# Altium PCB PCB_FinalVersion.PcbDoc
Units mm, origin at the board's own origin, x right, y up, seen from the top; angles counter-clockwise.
Board outline 269.9 x 119.9 mm, 2 copper layers (Top Layer, Bottom Layer); 58 components, 78 nets, 213 pads, 10 vias.
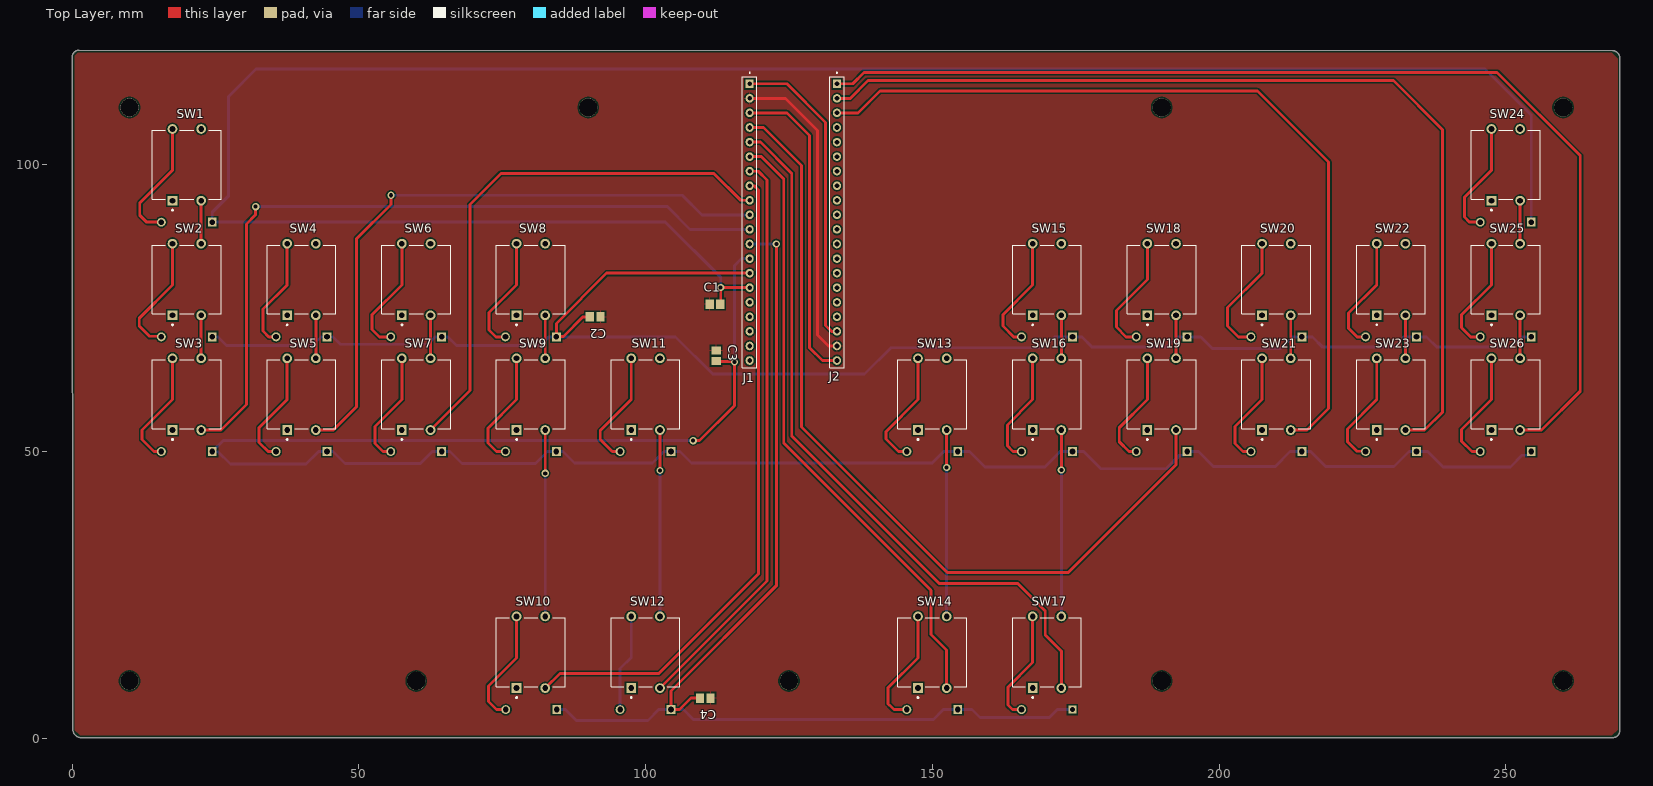
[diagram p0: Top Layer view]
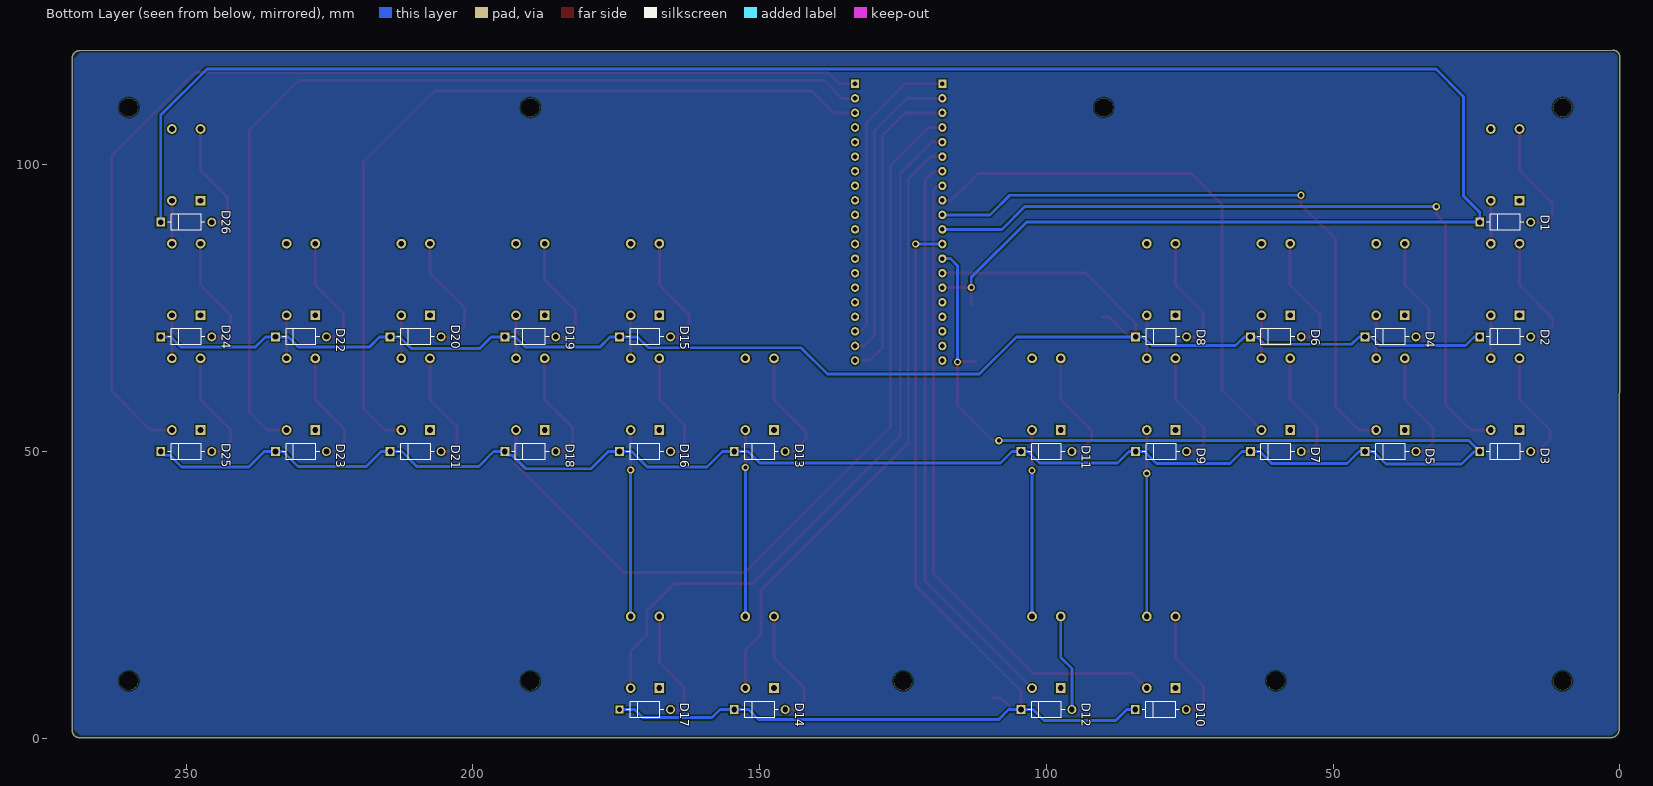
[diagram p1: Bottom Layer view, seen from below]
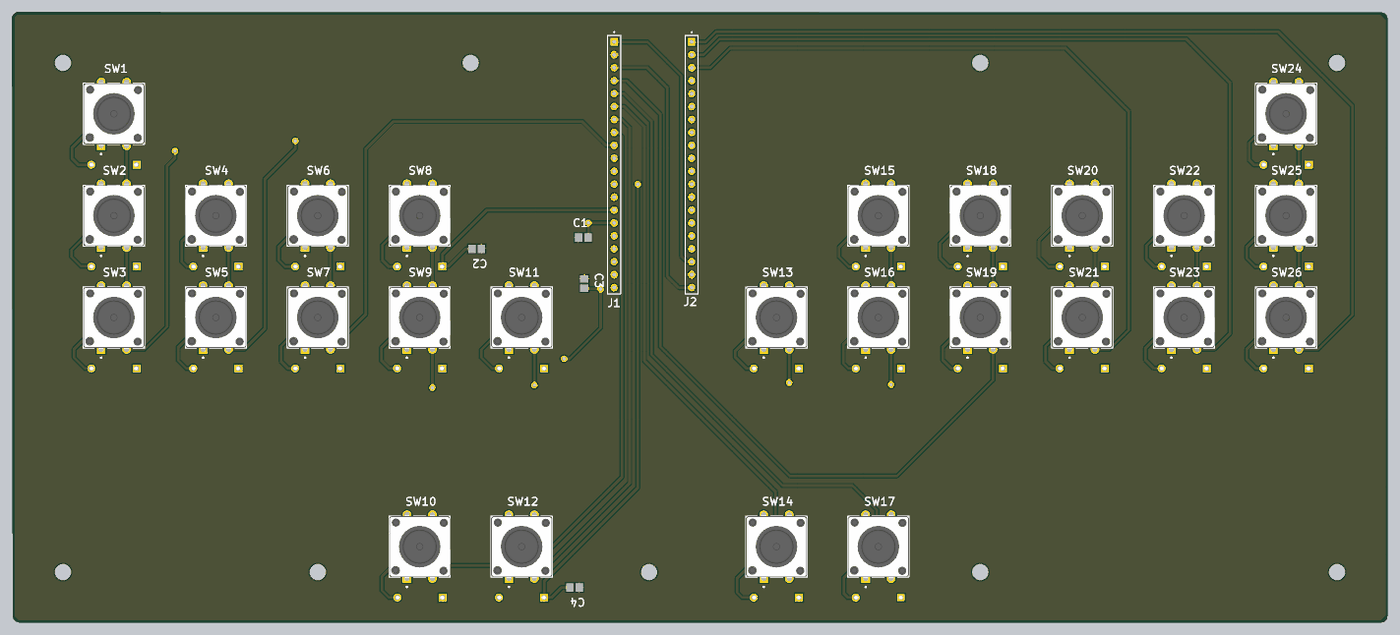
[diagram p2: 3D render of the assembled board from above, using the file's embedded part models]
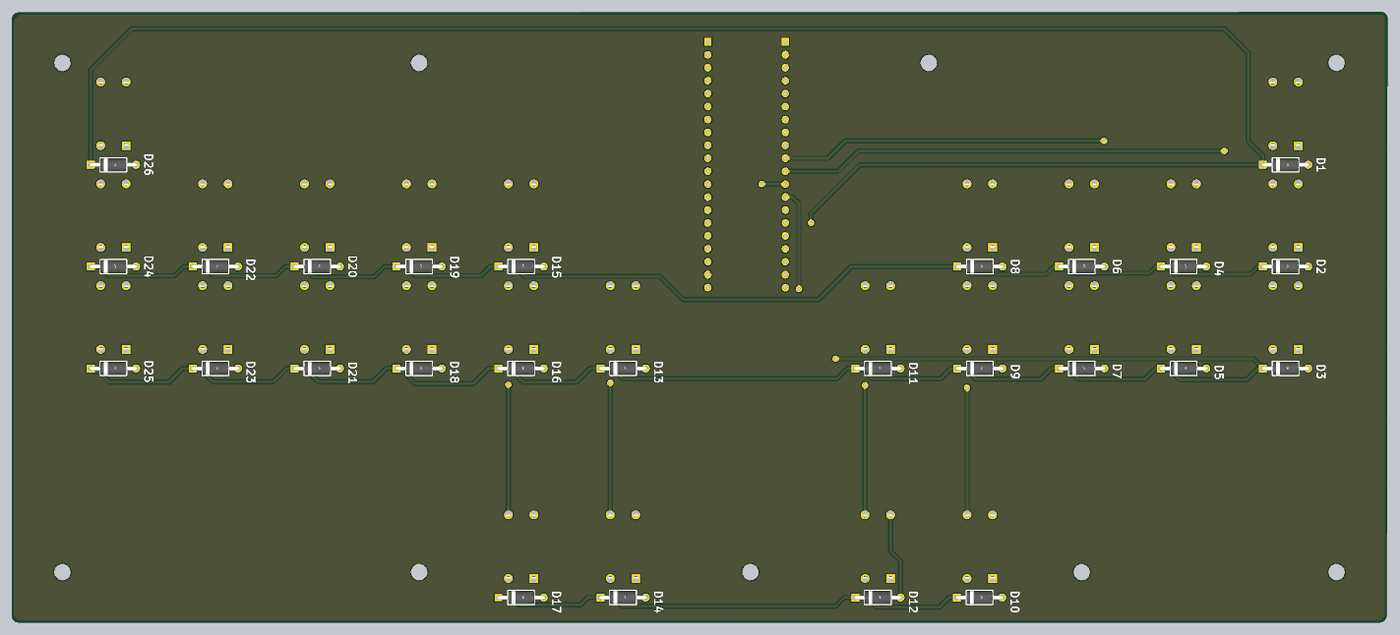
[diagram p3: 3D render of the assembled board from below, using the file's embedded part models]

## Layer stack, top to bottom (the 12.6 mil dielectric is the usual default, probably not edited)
Top Solder: solder mask 0.0102, Solder Resist, Dk 3.5
Top Layer: signal copper 0.0356
Dielectric 1: dielectric 0.32, FR-4, Dk 4.8
Bottom Layer: signal copper 0.0356
Bottom Solder: solder mask 0.0102, Solder Resist, Dk 3.5

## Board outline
0.129,1.541 ccw(c1.57,1.541) 1.57,0.1 5,0.1 268.63,0.1 ccw(c268.63,1.37) 269.9,1.37 269.9,118.63 ccw(c268.63,118.63) 268.63,119.9 1.217,120 ccw(c1.217,118.783) 0,118.783

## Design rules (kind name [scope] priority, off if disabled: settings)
Clearance [All] p1: gap=0.254 ignorepadtopadclearanceinfootprint=FALSE except(0: Arc-Hole Track-Hole SMDPad-Hole THPad-Hole Via-Hole Fill-Hole Poly-Hole Region-Hole Text-Hole)
PolygonConnect [All] p1: connectstyle=Relief reliefconductorwidth=0.254 reliefentries=4 polygonreliefangle="90 Angle" airgapwidth=0.254
RoutingVias [All] p1: holewidth=0.711 width=1.27 viastyle="Through Hole" minholewidth=0.711 minwidth=1.27 maxholewidth=0.711 maxwidth=1.27
SolderMaskExpansion [All] p1: expansion=0.102 istentingtop=FALSE
Width [All] p1: maxlimit=0.5 minlimit=0.254 preferedwidth=0.3
30 further rules are at their usual default settings.

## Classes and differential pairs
component class Sheet1: * A B C1 C2 C3 C4 D D1 D2 D3 D4 D5 D6 D7 D8 D9 D10 D11 D12 D13 D14 D15 D16 D17 D18 D19 D20 D21 D22 D23 D24 D25 D26 E F G H J1 J2 K L O P R S "Special 1" "Special 2" T U W Z

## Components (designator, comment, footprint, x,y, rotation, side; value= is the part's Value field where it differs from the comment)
C1 "TACR107M003XTA" CAPC2014X150X70ML20 112.1,75.7 r0 top
C2 "TACR107M003XTA" CAPC2014X150X70ML20 91.2,73.5 r180 top
C3 "TACR107M003XTA" CAPC2014X150X70ML20 112.3,66.7 r270 top
C4 "TACR107M003XTA" CAPC2014X150X70ML20 110.4,7 r180 top
D1 "1N4007" FP-1N4007-MFG#1 20,90 r180 bottom value=15pF
D2 "1N4007" FP-1N4007-MFG#1 20,70 r180 bottom value=15pF
D3 "1N4007" FP-1N4007-MFG#1 20,50 r180 bottom value=15pF
D4 "1N4007" FP-1N4007-MFG#1 40,70 r180 bottom value=15pF
D5 "1N4007" FP-1N4007-MFG#1 40,50 r180 bottom value=15pF
D6 "1N4007" FP-1N4007-MFG#1 60,70 r180 bottom value=15pF
D7 "1N4007" FP-1N4007-MFG#1 60,50 r180 bottom value=15pF
D8 "1N4007" FP-1N4007-MFG#1 80,70 r180 bottom value=15pF
D9 "1N4007" FP-1N4007-MFG#1 80,50 r180 bottom value=15pF
D10 "1N4007" FP-1N4007-MFG#1 80.061,5 r180 bottom value=15pF
D11 "1N4007" FP-1N4007-MFG#1 100,50 r180 bottom value=15pF
D12 "1N4007" FP-1N4007-MFG#1 100,5 r180 bottom value=15pF
D13 "1N4007" FP-1N4007-MFG#1 150,50 r180 bottom value=15pF
D14 "1N4007" FP-1N4007-MFG#1 150,5 r180 bottom value=15pF
D15 "1N4007" FP-1N4007-MFG#1 170,70 r180 bottom value=15pF
D16 "1N4007" FP-1N4007-MFG#1 170,50 r180 bottom value=15pF
D17 "1N4007" FP-1N4007-MFG#2 170,5 r180 bottom value=15pF
D18 "1N4007" FP-1N4007-MFG#1 190,50 r180 bottom value=15pF
D19 "1N4007" FP-1N4007-MFG#1 190,70 r180 bottom value=15pF
D20 "1N4007" FP-1N4007-MFG#1 210,70 r180 bottom value=15pF
D21 "1N4007" FP-1N4007-MFG#1 210,50 r180 bottom value=15pF
D22 "1N4007" FP-1N4007-MFG#1 230,70 r180 bottom value=15pF
D23 "1N4007" FP-1N4007-MFG#1 230,50 r180 bottom value=15pF
D24 "1N4007" FP-1N4007-MFG#1 250,70 r180 bottom value=15pF
D25 "1N4007" FP-1N4007-MFG#1 250,50 r180 bottom value=15pF
D26 "1N4007" FP-1N4007-MFG#1 250,90 r180 bottom value=15pF
J1 "TS-120-T-AA" SAMTEC_TS-120-T-AA 118.156,90 r270 top
J2 "TS-120-T-AA" SAMTEC_TS-120-T-AA 133.376,90 r270 top
SW1 "MJTP1212A" FP-MJTP1212A-MFG 20,100 r90 top
SW2 "MJTP1212A" FP-MJTP1212A-MFG 20,80 r90 top
SW3 "MJTP1212A" FP-MJTP1212A-MFG 20,60 r90 top
SW4 "MJTP1212A" FP-MJTP1212A-MFG 40,80 r90 top
SW5 "MJTP1212A" FP-MJTP1212A-MFG 40,60 r90 top
SW6 "MJTP1212A" FP-MJTP1212A-MFG 60,80 r90 top
SW7 "MJTP1212A" FP-MJTP1212A-MFG 60,60 r90 top
SW8 "MJTP1212A" FP-MJTP1212A-MFG 80,80 r90 top
SW9 "MJTP1212A" FP-MJTP1212A-MFG 80,60 r90 top
SW10 "MJTP1212A" FP-MJTP1212A-MFG 80,15 r90 top
SW11 "MJTP1212A" FP-MJTP1212A-MFG 100,60 r90 top
SW12 "MJTP1212A" FP-MJTP1212A-MFG 100,15 r90 top
SW13 "MJTP1212A" FP-MJTP1212A-MFG 150,60 r90 top
SW14 "MJTP1212A" FP-MJTP1212A-MFG 150,15 r90 top
SW15 "MJTP1212A" FP-MJTP1212A-MFG 170,80 r90 top
SW16 "MJTP1212A" FP-MJTP1212A-MFG 170,60 r90 top
SW17 "MJTP1212A" FP-MJTP1212A-MFG 170,15 r90 top
SW18 "MJTP1212A" FP-MJTP1212A-MFG 190,80 r90 top
SW19 "MJTP1212A" FP-MJTP1212A-MFG 190,60 r90 top
SW20 "MJTP1212A" FP-MJTP1212A-MFG 210,80 r90 top
SW21 "MJTP1212A" FP-MJTP1212A-MFG 210,60 r90 top
SW22 "MJTP1212A" FP-MJTP1212A-MFG 230,80 r90 top
SW23 "MJTP1212A" FP-MJTP1212A-MFG 230,60 r90 top
SW24 "MJTP1212A" FP-MJTP1212A-MFG 250,100 r90 top
SW25 "MJTP1212A" FP-MJTP1212A-MFG 250,80 r90 top
SW26 "MJTP1212A" FP-MJTP1212A-MFG 250,60 r90 top

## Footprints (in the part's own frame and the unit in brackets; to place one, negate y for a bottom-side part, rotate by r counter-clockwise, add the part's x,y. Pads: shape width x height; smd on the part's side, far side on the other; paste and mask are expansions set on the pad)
CAPC2014X150X70ML20 [mm] "Chip Capacitor, 2-Leads, Body 2.00x1.35mm, IPC Low Density"
  rect 1.45x1.65 smd: 1(-0.925,0) 2(0.925,0)
  body extent -1.1,-0.77 1.1,0.77, height 1.5
FP-1N4007-MFG#1 [mm]
  rect 1.55x1.55 hole 1 paste-2539.97 mask+0: 1(-4.44,0)
  round 1.55 hole 1 paste-2539.97 mask+0: 2(4.44,0)
  silkscreen extent -3.27,-1.4 3.27,1.4, body extent -4.83,-1.29 4.83,1.29, height 2.6
FP-1N4007-MFG#2 [mm]
  rect 1.4x1.4 hole 0.9 paste-2539.97 mask+0: 1(-4.44,0)
  round 1.55 hole 1 paste-2539.97 mask+0: 2(4.44,0)
  silkscreen extent -3.27,-1.4 3.27,1.4, body extent -4.83,-1.29 4.83,1.29, height 2.6
FP-MJTP1212A-MFG [mm]
  rect 1.7x1.7 hole 1 paste-2539.97 mask+0: 1(-6.25,2.5)
  round 1.7 hole 1 paste-2539.97 mask+0: 2(6.25,2.5) 3(-6.25,-2.5) 4(6.25,-2.5)
  silkscreen extent -8.02,-6 6,6, body extent -7.27,-6.1 7.27,6.1, height 0.25
SAMTEC_TS-120-T-AA [mm]
  rect 1.5x1.4 hole 0.8: 01(-24.13,0)
  oval 1.5x1.4 hole 0.8: 02(-21.59,0) 03(-19.05,0) 04(-16.51,0) 05(-13.97,0) 06(-11.43,0) 07(-8.89,0) 08(-6.35,0) 09(-3.81,0) 10(-1.27,0) 11(1.27,0) 12(3.81,0) 13(6.35,0) 14(8.89,0) 15(11.43,0) 16(13.97,0) 17(16.51,0) 18(19.05,0) 19(21.59,0) 20(24.13,0)
  silkscreen extent -26.15,-1.27 25.4,1.27

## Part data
C1 C2 C3 C4: library part CMP-2007-00028-1, Manufacturer="AVX Interconnect / Elco"
D1 D2 D3 D4 D5 D6 D7 D8 D9 D10 D11 D12 D13 D14 D15 D16 D17 D18 D19 D20 D21 D22 D23 D24 D25 D26: library part CMP-123542-000001-1, "Rectifier diode 1000 V 1 A DO-41, ,", Capacitance=15pF, Forward Current=1A, Manufacturer=Diotec, Max Junction Temp=+175°C, Max Repetitive Reverse Voltage=1000V, Max Surge Forward Current=27A, Peak Reverse Current=5uA, Temperature="-50°C to +175°C", Temperature Range Low=-50°C
J1 J2: "Headers & Wire Housings .100 Single Row Screw Machine Terminal Strip", Package=None
SW1 SW2 SW3 SW4 SW5 SW6 SW7 SW8 SW9 SW10 SW11 SW12 SW13 SW14 SW15 SW16 SW17 SW18 SW19 SW20 SW21 SW22 SW23 SW24 SW25 SW26: library part CMP-47024-000003-1, "SWITCH TACTILE SPST-NO 0.05A 12V", Contact Resistance=100mR, Current Rating=50mA, Max Operating Temperature=70°C, Max Voltage Rating (DC)=12V, Min Operating Temperature=-20°C, Operating Force=160gf, Package Quantity=100

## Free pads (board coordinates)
  round 3.2 hole 3.2: 4(10,10) 4(10,110) 4(60,10) 4(90,110) 4(125,10) 4(190,10) 4(190,110) 4(260,10) 4(260,110)

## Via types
v1: diameter 1.27, hole 0.711, Top Layer to Bottom Layer, 10 vias

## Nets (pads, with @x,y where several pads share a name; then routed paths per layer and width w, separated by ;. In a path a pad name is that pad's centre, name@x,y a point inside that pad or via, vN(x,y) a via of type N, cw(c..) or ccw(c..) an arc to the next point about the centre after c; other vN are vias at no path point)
3.3V: J1.03 J2.20 | length 54.8
  Top Layer w0.5: J1.03 124.65,109.05 128.6,105.1 128.6,68.1 130.83,65.87 J2.20
5V: J1.01 J2.18 | length 53.8
  Top Layer w0.5: J1.01 124.67,114.13 131.4,107.4 131.4,72 132.45,70.95 J2.18
A8: J2.05
A9: J2.06
A10: J2.07
A11: J2.08
A12: J2.09
A15: J2.10
B3: J2.11
B4: J2.12
B5: J2.13
B6: J2.14
B7: J2.15
B8: J2.16
B9: J2.17
B15: J2.04
C13: J1.19
C14: J1.18
C15: J1.17
Column1: J1.11 SW3.3 | length 132.7
  Top Layer w0.5: SW3.3 25.95,53.75 30.4,58.2 30.4,89.7 32,91.3 v1(32,92.7)
  Bottom Layer w0.5: v1(32,92.7) 103.8,92.7 107.77,88.73 J1.11
Column2: J1.10 SW5.3 | length 112.1
  Top Layer w0.5: SW5.3 45.55,53.75 49.6,57.8 49.6,87.1 55.6,93.1 v1(55.6,94.7)
  Bottom Layer w0.5: v1(55.6,94.7) 106.4,94.7 109.83,91.27 J1.10
Column3: J1.09 SW7.3 | length 95.1
  Top Layer w0.5: SW7.3 69.4,60.65 69.4,93.1 74.8,98.5 111.9,98.5 116.59,93.81 J1.09
Column4: J1.08 SW10.3 | length 114.2
  Top Layer w0.5: SW10.3 85.05,11.3 102.3,11.3 119.7,28.7 119.7,95.6 118.95,96.35 J1.08
Column5: J1.07 SW12.3 | length 100
  Top Layer w0.5: SW12.3 121.2,27.45 121.2,97.33 119.64,98.89 J1.07
Column6: J1.06 SW14.3 | length 108.1
  Top Layer w0.5: J1.06 120.17,101.43 124.1,97.5 124.1,51.5 149.8,25.8 149.8,18.091 152.5,15.391 SW14.3
Column7: J1.05 SW17.3 | length 126.9
  Top Layer w0.5: J1.05 120.03,103.97 125.5,98.5 125.5,52.7 151.2,27 164.9,27 169.7,22.2 169.7,18 172.5,15.2 SW17.3
Column8: J1.04 SW19.3 | length 147
  Top Layer w0.5: J1.04 120.59,106.51 127.2,99.9 127.2,54.3 152.6,28.9 173.7,28.9 192.5,47.7 SW19.3
Column9: J2.03 SW21.3 | length 143.6
  Top Layer w0.5: J2.03 137.05,109.05 140.9,112.9 206.7,112.9 219.1,100.5 219.1,57.5 215.35,53.75 SW21.3
Column10: J2.02 SW23.3 | length 167.5
  Top Layer w0.5: J2.02 135.69,111.59 138.8,114.7 230.4,114.7 239,106.1 239,56.9 235.85,53.75 SW23.3
Column11: J2.01 SW26.3 | length 190.8
  Top Layer w0.5: J2.01 136.13,114.13 138.1,116.1 248.5,116.1 263,101.6 263,60.5 256.25,53.75 SW26.3
GND: C1.1 C2.1 C3.1 C4.1 J1.02 J2.19 | length 54
  Top Layer w0.5: J1.02 124.41,111.59 130,106 130,70.3 131.89,68.41 J2.19
NetD1_2: D1.2 SW1.2 | length 21.7
  Top Layer w0.5: D1.2 13,90 11.8,91.2 11.8,93.354 17.5,99.054 SW1.2
NetD2_2: D2.2 SW2.2 | length 21.4
  Top Layer w0.5: D2.2 15.462,70.098 13.502,70.098 11.7,71.9 11.7,73.254 17.5,79.054 SW2.2
NetD3_2: D3.2 SW3.2 | length 20.6
  Top Layer w0.5: D3.2 14.3,50 12.2,52.1 12.2,53.754 17.5,59.054 SW3.2
NetD4_2: D4.2 SW4.2 | length 19.7
  Top Layer w0.5: D4.2 34.3,70 33.3,71 33.3,74.854 37.5,79.054 SW4.2
NetD5_2: D5.2 SW5.2 | length 20.3
  Top Layer w0.5: D5.2 34.2,50 32.6,51.6 32.6,54.154 37.5,59.054 SW5.2
NetD6_2: D6.2 SW6.2 | length 20.9
  Top Layer w0.5: D6.2 53.6,70 52.3,71.3 52.3,73.854 57.5,79.054 SW6.2
NetD7_2: D7.2 SW7.2 | length 20.1
  Top Layer w0.5: D7.2 54.2,50 52.8,51.4 52.8,54.354 57.5,59.054 SW7.2
NetD8_2: D8.2 SW8.2 | length 20.4
  Top Layer w0.5: D8.2 73.9,70 72.7,71.2 72.7,74.254 77.5,79.054 SW8.2
NetD9_2: D9.2 SW9.2 | length 20.5
  Top Layer w0.5: D9.2 74,50 72.5,51.5 72.5,54.054 77.5,59.054 SW9.2
NetD10_2: D10.2 SW10.2 | length 20.5
  Top Layer w0.5: D10.2 74,5 72.6,6.4 72.6,9.124 77.5,14.024 SW10.2
NetD11_2: D11.2 SW11.2 | length 20.7
  Top Layer w0.5: D11.2 94.2,50 92.1,52.1 92.1,53.654 97.5,59.054 SW11.2
NetD12_2: D12.2 SW12.2 | length 17.1
  Bottom Layer w0.5: D12.2 95.56,12.16 97.5,14.1 SW12.2
NetD13_2: D13.2 SW13.2 | length 20.9
  Top Layer w0.5: D13.2 144.1,50 141.9,52.2 141.9,53.454 147.5,59.054 SW13.2
NetD14_2: D14.2 SW14.2 | length 21.1
  Top Layer w0.5: D14.2 143.3,5 142.6,5.7 142.593,5.7 142.3,5.993 142.3,8.8 147.5,14 SW14.2
NetD15_2: D15.2 SW15.2 | length 20.6
  Top Layer w0.5: D15.2 164.2,70 162.3,71.9 162.3,73.854 167.5,79.054 SW15.2
NetD16_2: D16.2 SW16.2 | length 19.9
  Top Layer w0.5: D16.2 164.1,50 163.1,51 163.1,54.654 167.5,59.054 SW16.2
NetD17_2: D17.2 SW17.2 | length 19.9
  Top Layer w0.5: D17.2 164,5 163.2,5.8 163.2,8.9 167.5,13.2 SW17.2
NetD18_2: D18.2 SW19.2 | length 20.2
  Top Layer w0.5: D18.2 184.3,50 182.6,51.7 182.6,54.154 187.5,59.054 SW19.2
NetD19_2: D19.2 SW18.2 | length 21
  Top Layer w0.5: D19.2 183.8,70 182.1,71.7 182.1,74.6 187.5,80 SW18.2
NetD20_2: D20.2 SW20.2 | length 21.7
  Top Layer w0.5: D20.2 203.4,70 201.5,71.9 201.5,75.1 207.5,81.1 SW20.2
NetD21_2: D21.2 SW21.2 | length 20.1
  Top Layer w0.5: D21.2 204.2,50 202.8,51.4 202.8,54.354 207.5,59.054 SW21.2
NetD22_2: D22.2 SW22.2 | length 20.4
  Top Layer w0.5: D22.2 224.1,70 222.6,71.5 222.6,74.154 227.5,79.054 SW22.2
NetD23_2: D23.2 SW23.2 | length 20.5
  Top Layer w0.5: D23.2 225.512,50.048 224.052,50.048 222.4,51.7 222.4,53.954 227.5,59.054 SW23.2
NetD24_2: D24.2 SW25.2 | length 20.7
  Top Layer w0.5: D24.2 243.9,70 242.3,71.6 242.3,73.854 247.5,79.054 SW25.2
NetD25_2: D25.2 SW26.2 | length 20.6
  Top Layer w0.5: D25.2 244.1,50 242.3,51.8 242.3,53.854 247.5,59.054 SW26.2
NetD26_2: D26.2 SW24.2 | length 20.4
  Top Layer w0.5: D26.2 243.7,90 242.8,90.9 242.8,94.354 247.5,99.054 SW24.2
NetSW1_3: SW1.3 SW2.4 | length 7.5
  Top Layer w0.5: SW2.4 SW1.3
NetSW2_3: SW2.3 SW3.4 | length 7.5
  Top Layer w0.5: SW3.4 SW2.3
NetSW4_3: SW4.3 SW5.4 | length 7.5
  Top Layer w0.5: SW5.4 SW4.3
NetSW6_3: SW6.3 SW7.4 | length 7.5
  Top Layer w0.5: SW7.4 SW6.3
NetSW8_3: SW8.3 SW9.4 | length 7.5
  Top Layer w0.5: SW9.4 SW8.3
NetSW9_3: SW9.3 SW10.4 | length 32.5
  Top Layer w0.5: v1(82.5,46.2) SW9.3
  Bottom Layer w0.5: SW10.4 v1(82.5,46.2)
NetSW11_3: SW11.3 SW12.4 | length 32.5
  Top Layer w0.5: v1(102.5,46.7) SW11.3
  Bottom Layer w0.5: SW12.4 v1(102.5,46.7)
NetSW13_3: SW13.3 SW14.4 | length 32.5
  Top Layer w0.5: v1(152.5,47.2) SW13.3
  Bottom Layer w0.5: SW14.4 v1(152.5,47.2)
NetSW15_3: SW15.3 SW16.4 | length 7.5
  Top Layer w0.5: SW16.4 SW15.3
NetSW16_3: SW16.3 SW17.4 | length 32.5
  Top Layer w0.5: v1(172.5,46.8) SW16.3
  Bottom Layer w0.5: SW17.4 v1(172.5,46.8)
NetSW18_3: SW18.3 SW19.4 | length 7.5
  Top Layer w0.5: SW19.4 SW18.3
NetSW20_3: SW20.3 SW21.4 | length 7.5
  Top Layer w0.5: SW21.4 SW20.3
NetSW22_3: SW22.3 SW23.4 | length 7.5
  Top Layer w0.5: SW23.4 SW22.3
NetSW24_3: SW24.3 SW25.4 | length 7.5
  Top Layer w0.5: SW25.4 SW24.3
NetSW25_3: SW25.3 SW26.4 | length 7.5
  Top Layer w0.5: SW26.4 SW25.3
R: J1.16
Row1: C1.2 D1.1 D26.1 J1.15 | length 376.8
  Top Layer w0.5: C1.2@112.925,75.7 113.1,75.875 v1(113.1,78.6) 113.115,78.585 118.141,78.585 J1.15 ; D26.1 D26.1@254.53,90.09
  Bottom Layer w0.5: v1(113.1,78.6) 113.1,80.4 103.5,90 D1.1 24.44,91.74 27.3,94.6 27.3,111.928 32.072,116.7 246.4,116.7 254.44,108.66 D26.1
Row2: C2.2 D2.1 D4.1 D6.1 D8.1 D15.1 D19.1 D20.1 D22.1 D24.1 J1.14 | length 292.1
  Top Layer w0.5: C2.2 90.268,73.493 89.093,73.493 85.672,70.072 84.512,70.072 D8.1 84.44,72.34 93.21,81.11 J1.14
  Bottom Layer w0.5: D2.1 24.487,69.953 25.447,69.953 26.9,68.5 41.9,68.5 43.4,70 45.5,70 46.8,68.7 62,68.7 63.3,70 65.5,70 67,68.5 81.6,68.5 83.1,70 D8.1 105.2,70 111.7,63.5 138.2,63.5 142.8,68.1 169.4,68.1 171.3,70 D15.1 176.1,70 177.9,68.2 190.8,68.2 192.6,70 D19.1 196.8,70 198.8,68 210.8,68 212.8,70 D20.1 216.3,70 218.1,68.2 230.4,68.2 232.2,70 D22.1 236.2,70 238,68.2 250.9,68.2 252.7,70 D24.1
Row3: C3.2 D3.1 D5.1 D7.1 D9.1 D11.1 D13.1 D16.1 D18.1 D21.1 D23.1 D25.1 J1.13 | length 375.1
  Top Layer w0.5: D3.1@24.39,49.95 D3.1 ; v1(108.3,51.9) 109.4,51.9 115.5,58 v1(115.5,65.6) 115.412,65.688 112.488,65.688 C3.2@112.4,65.775
  Bottom Layer w0.5: v1(108.3,51.9) 26.34,51.9 D3.1 24.487,49.953 25.447,49.953 27.6,47.8 40.8,47.8 43,50 D5.1 45.5,50 47.6,47.9 60.7,47.9 62.8,50 D7.1 65.9,50 68,47.9 80.8,47.9 82.9,50 D9.1 85.6,50 87.6,48 101.2,48 103.2,50 D11.1 106,50 108,48 150,48 152,50 D13.1 156.5,50 159.2,47.3 169.6,47.3 172.3,50 D16.1 176.4,50 179.4,47 190.8,47 193.152,49.352 193.792,49.352 D18.1 196.4,50 199,47.4 209.8,47.4 212.4,50 D21.1 216,50 218.6,47.4 230.5,47.4 233.1,50 D23.1 236.4,50 239.1,47.3 250.8,47.3 252.852,49.352 253.792,49.352 D25.1 ; v1(115.5,65.6) 115.5,82.4 116.75,83.65 J1.13
Row4: C4.2 D10.1 D12.1 D14.1 D17.1 J1.12 | length 193.4
  Top Layer w0.5: C4.2 107.9,7 105.9,5 D12.1 104.44,8.24 122.8,26.6 v1(122.8,86.2)
  Bottom Layer w0.5: D10.1 86,5 87.9,3.1 100.4,3.1 102.3,5 D12.1 106.6,5 108.3,3.3 150.2,3.3 151.9,5 D14.1 156.9,5 158.3,3.6 170.4,3.6 171.8,5 D17.1 ; J1.12 118.161,86.195 122.795,86.195 v1(122.8,86.2)
VB: J1.20
pads on no net: SW1.1 SW1.4 SW2.1 SW3.1 SW4.1 SW4.4 SW5.1 SW6.1 SW6.4 SW7.1 SW8.1 SW8.4 SW9.1 SW10.1 SW11.1 SW11.4 SW12.1 SW13.1 SW13.4 SW14.1 SW15.1 SW15.4 SW16.1 SW17.1 SW18.1 SW18.4 SW19.1 SW20.1 SW20.4 SW21.1 SW22.1 SW22.4 SW23.1 SW24.1 SW24.4 SW25.1 SW26.1

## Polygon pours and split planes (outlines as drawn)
GND on Bottom Layer "GND_L02_P001" (solid, pour order 1): 1,119.5 0.5,119 0.5,1.4 1.4,0.5 268.5,0.5 269.5,1.5 269.5,118.5 268.5,119.5
GND on Top Layer "GND_L01_P000" (solid, pour order 0): 1,119.5 0.5,119 0.5,1.4 1.4,0.5 268.5,0.5 269.5,1.5 269.5,118.5 268.5,119.5

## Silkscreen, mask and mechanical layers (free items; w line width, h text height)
Mechanical 1:
  lines w0.254: 5,0.1 5.2,0.1 268.63,0.1 ccw(c268.63,1.37) 269.9,1.37 269.9,1.7 269.9,118.63 ccw(c268.63,118.63) 268.63,119.9 1.217,120 ccw(c1.217,118.783) 0,118.783 0.129,1.541 ccw(c1.57,1.541) 1.57,0.1 5,0.1 ; 5,0.1 5,0.1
